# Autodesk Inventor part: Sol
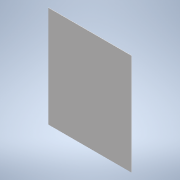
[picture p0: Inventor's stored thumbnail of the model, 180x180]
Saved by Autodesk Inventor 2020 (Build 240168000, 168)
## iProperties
Created: 2021-01
Part Number: Sol
Material: Générique
Document SubType Name: Modeling
Designer: bruno
Density: 1 g/cm^3
Appearance: Par défaut
Author: bruno
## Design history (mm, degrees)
node "Plan de construction1"
sketch "Esquisse1"
  geometry: L1 (-1518.226, 2185.843)-(784.377, 2185.843); L2 (784.377, 2185.843)-(784.377, -620.22); L3 (784.377, -620.22)-(-1518.226, -620.22); L4 (-1518.226, -620.22)-(-1518.226, 2185.843); 1 further point
  constraints: 8 end point, 2 parallel, 1 horizontal, 1 perpendicular
extrude "Extrusion1" new body sketch "Esquisse1" distance "d0" = 10; taper "d1" = 0 deg
node "Solide1"
